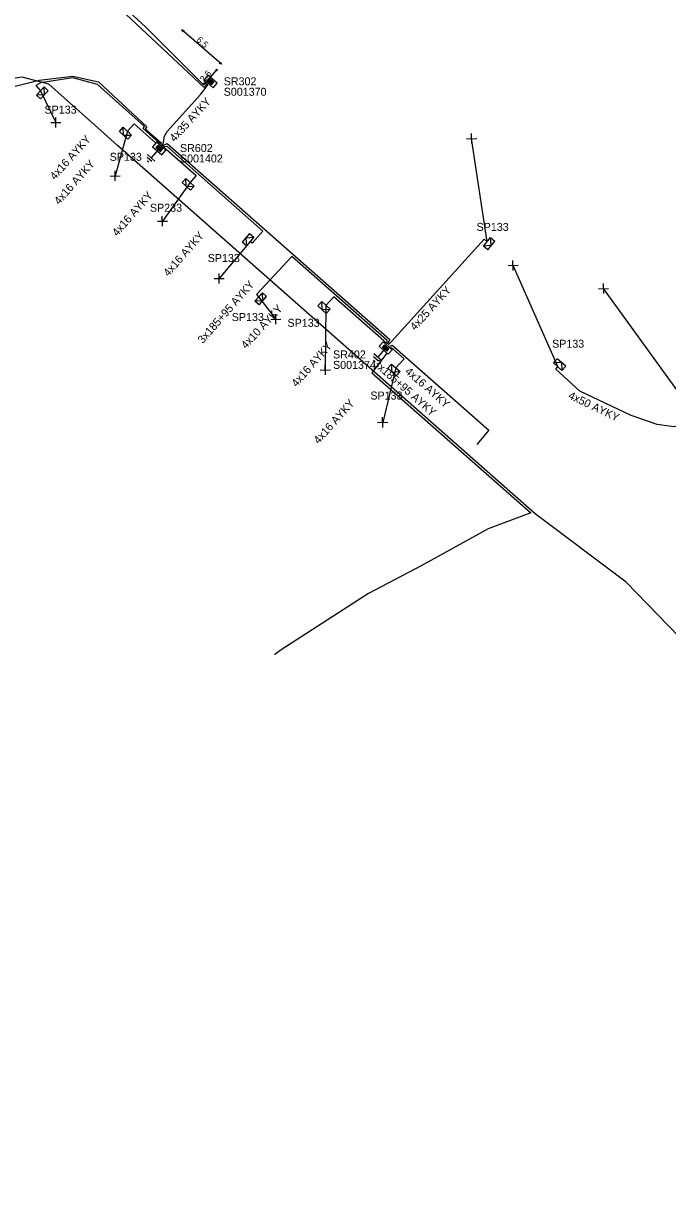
# Model space of a CAD drawing. Extents: x -762284 to -761419, y -1155250 to -1154991.
# Drawn here: x -761812.4 to -761732.3, y -1155246.2 to -1155100.2 of the extents above; entities that cross this region are included whole.
import ezdxf

# ---------------------------------------------------------------- set-up
doc = ezdxf.new("R2010")
doc.units = 0
for name, color, linetype in [('Vrstva 15', 7, 'Continuous'), ('Vrstva 28', 7, 'Continuous'), ('Vrstva 29', 7, 'Continuous'), ('Vrstva 30', 7, 'Continuous'), ('Vrstva 31', 7, 'Continuous'), ('Vrstva 33', 7, 'Continuous'), ('Vrstva 34', 7, 'Continuous'), ('Vrstva 40', 7, 'Continuous'), ('Vrstva 5', 7, 'Continuous'), ('Vrstva 59', 7, 'Continuous'), ('Vrstva 6', 7, 'Continuous')]:
    doc.layers.add(name, color=color, linetype=linetype)

msp = doc.modelspace()

# ---------------------------------------------------------------- linework, layer by layer
at = {"layer": 'Vrstva 15'}
for points in [[(-761795.667, -1155115.926), (-761796.487, -1155116.869)], [(-761796.4, -1155117.355), (-761796.995, -1155116.838)], [(-761796.897, -1155117.341), (-761796.993, -1155117.257)], [(-761796.015, -1155117.279), (-761796.958, -1155116.459)], [(-761796.796, -1155117.428), (-761796.897, -1155117.341)], [(-761767.506, -1155140.716), (-761768.327, -1155141.66)], [(-761768.24, -1155142.146), (-761768.835, -1155141.629)], [(-761768.737, -1155142.131), (-761768.833, -1155142.047)], [(-761767.855, -1155142.07), (-761768.798, -1155141.25)], [(-761768.636, -1155142.219), (-761768.737, -1155142.131)]]:
    msp.add_lwpolyline(points, dxfattribs=at)
at = {"layer": 'Vrstva 28'}
for points in [[(-761789.436, -1155106.625), (-761789.918, -1155107.2)], [(-761789.918, -1155107.2), (-761788.769, -1155108.164)], [(-761789.264, -1155107.017), (-761789.507, -1155107.306)], [(-761789.507, -1155107.306), (-761788.937, -1155107.784)], [(-761789.258, -1155107.083), (-761789.44, -1155107.3)], [(-761789.44, -1155107.3), (-761788.942, -1155107.718)], [(-761788.287, -1155107.589), (-761789.436, -1155106.625)], [(-761789.252, -1155107.15), (-761789.374, -1155107.294)], [(-761789.374, -1155107.294), (-761788.948, -1155107.651)], [(-761789.246, -1155107.216), (-761789.307, -1155107.289)], [(-761789.307, -1155107.289), (-761788.954, -1155107.585)], [(-761788.694, -1155107.495), (-761789.264, -1155107.017)], [(-761788.76, -1155107.501), (-761789.258, -1155107.083)], [(-761788.827, -1155107.507), (-761789.252, -1155107.15)], [(-761788.893, -1155107.512), (-761789.246, -1155107.216)], [(-761788.955, -1155107.522), (-761789.245, -1155107.279)], [(-761788.954, -1155107.585), (-761788.893, -1155107.512)], [(-761788.948, -1155107.651), (-761788.827, -1155107.507)], [(-761788.942, -1155107.718), (-761788.76, -1155107.501)], [(-761788.937, -1155107.784), (-761788.694, -1155107.495)], [(-761788.769, -1155108.164), (-761788.287, -1155107.589)], [(-761795.812, -1155114.947), (-761796.304, -1155115.513)], [(-761796.304, -1155115.513), (-761795.172, -1155116.497)], [(-761795.652, -1155115.329), (-761795.9, -1155115.614)], [(-761795.9, -1155115.614), (-761795.338, -1155116.103)], [(-761795.647, -1155115.396), (-761795.833, -1155115.61)], [(-761795.833, -1155115.61), (-761795.343, -1155116.036)], [(-761794.68, -1155115.931), (-761795.812, -1155114.947)], [(-761795.642, -1155115.463), (-761795.766, -1155115.605)], [(-761795.766, -1155115.605), (-761795.347, -1155115.969)], [(-761795.638, -1155115.529), (-761795.7, -1155115.6)], [(-761795.7, -1155115.6), (-761795.352, -1155115.903)], [(-761795.09, -1155115.817), (-761795.652, -1155115.329)], [(-761795.157, -1155115.822), (-761795.647, -1155115.396)], [(-761795.223, -1155115.827), (-761795.642, -1155115.463)], [(-761795.29, -1155115.831), (-761795.638, -1155115.529)], [(-761795.637, -1155115.592), (-761795.352, -1155115.84)], [(-761795.352, -1155115.903), (-761795.29, -1155115.831)], [(-761795.347, -1155115.969), (-761795.223, -1155115.827)], [(-761795.343, -1155116.036), (-761795.157, -1155115.822)], [(-761795.338, -1155116.103), (-761795.09, -1155115.817)], [(-761795.172, -1155116.497), (-761794.68, -1155115.931)], [(-761767.652, -1155139.737), (-761768.144, -1155140.303)], [(-761766.52, -1155140.721), (-761767.652, -1155139.737)], [(-761768.144, -1155140.303), (-761767.012, -1155141.287)], [(-761767.491, -1155140.119), (-761767.739, -1155140.405)], [(-761767.739, -1155140.405), (-761767.177, -1155140.893)], [(-761767.486, -1155140.186), (-761767.672, -1155140.4)], [(-761767.672, -1155140.4), (-761767.182, -1155140.826)], [(-761767.482, -1155140.253), (-761767.606, -1155140.395)], [(-761767.606, -1155140.395), (-761767.187, -1155140.759)], [(-761767.477, -1155140.319), (-761767.539, -1155140.391)], [(-761767.539, -1155140.391), (-761767.191, -1155140.693)], [(-761766.929, -1155140.608), (-761767.491, -1155140.119)], [(-761766.996, -1155140.612), (-761767.486, -1155140.186)], [(-761767.063, -1155140.617), (-761767.482, -1155140.253)], [(-761767.129, -1155140.622), (-761767.477, -1155140.319)], [(-761767.477, -1155140.382), (-761767.192, -1155140.63)], [(-761767.191, -1155140.693), (-761767.129, -1155140.622)], [(-761767.187, -1155140.759), (-761767.063, -1155140.617)], [(-761767.182, -1155140.826), (-761766.996, -1155140.612)], [(-761767.177, -1155140.893), (-761766.929, -1155140.608)], [(-761767.012, -1155141.287), (-761766.52, -1155140.721)]]:
    msp.add_lwpolyline(points, dxfattribs=at)
at = {"layer": 'Vrstva 31'}
for points in [[(-761810.227, -1155109.562), (-761810.739, -1155109.084), (-761809.784, -1155108.06), (-761809.273, -1155108.538)], [(-761809.75, -1155109.05), (-761810.739, -1155109.084)], [(-761810.227, -1155109.562), (-761809.273, -1155108.538)], [(-761809.75, -1155109.05), (-761809.784, -1155108.06)], [(-761800.432, -1155113.602), (-761799.954, -1155113.091), (-761798.931, -1155114.045), (-761799.408, -1155114.557)], [(-761799.92, -1155114.08), (-761799.954, -1155113.091)], [(-761800.432, -1155113.602), (-761799.408, -1155114.557)], [(-761799.92, -1155114.08), (-761798.931, -1155114.045)], [(-761792.642, -1155119.963), (-761792.165, -1155119.451), (-761791.141, -1155120.405), (-761791.618, -1155120.917)], [(-761792.642, -1155119.963), (-761791.618, -1155120.917)], [(-761792.13, -1155120.44), (-761792.165, -1155119.451)], [(-761792.13, -1155120.44), (-761791.141, -1155120.405)], [(-761784.257, -1155126.29), (-761785.175, -1155127.346)], [(-761784.257, -1155126.29), (-761783.729, -1155126.749), (-761784.647, -1155127.806), (-761785.175, -1155127.346)], [(-761784.716, -1155126.818), (-761783.729, -1155126.749)], [(-761784.716, -1155126.818), (-761784.647, -1155127.806)], [(-761754.655, -1155128.309), (-761755.191, -1155127.859), (-761754.292, -1155126.787), (-761753.755, -1155127.237)], [(-761754.205, -1155127.773), (-761755.191, -1155127.859)], [(-761754.655, -1155128.309), (-761753.755, -1155127.237)], [(-761754.205, -1155127.773), (-761754.292, -1155126.787)], [(-761783.08, -1155135.161), (-761783.6, -1155134.693), (-761782.663, -1155133.652), (-761782.143, -1155134.12)], [(-761782.612, -1155134.641), (-761782.663, -1155133.652)], [(-761782.612, -1155134.641), (-761783.6, -1155134.693)], [(-761783.08, -1155135.161), (-761782.143, -1155134.12)], [(-761775.752, -1155135.253), (-761775.274, -1155134.741), (-761774.25, -1155135.696), (-761774.728, -1155136.208)], [(-761775.752, -1155135.253), (-761774.728, -1155136.208)], [(-761775.24, -1155135.731), (-761775.274, -1155134.741)], [(-761775.24, -1155135.731), (-761774.25, -1155135.696)], [(-761767.061, -1155143.03), (-761766.593, -1155142.51), (-761765.553, -1155143.447), (-761766.021, -1155143.967)], [(-761766.541, -1155143.499), (-761766.593, -1155142.51)], [(-761744.96, -1155142.762), (-761745.42, -1155143.29), (-761746.476, -1155142.372), (-761746.017, -1155141.844)], [(-761745.489, -1155142.303), (-761746.476, -1155142.372)], [(-761744.96, -1155142.762), (-761746.017, -1155141.844)], [(-761745.489, -1155142.303), (-761745.42, -1155143.29)], [(-761767.061, -1155143.03), (-761766.021, -1155143.967)], [(-761766.541, -1155143.499), (-761765.553, -1155143.447)]]:
    msp.add_lwpolyline(points, dxfattribs=at)
at = {"layer": 'Vrstva 34'}
for points in [[(-761808.329, -1155113.125), (-761808.351, -1155111.875)], [(-761808.965, -1155112.511), (-761807.715, -1155112.489)], [(-761757.275, -1155114.501), (-761756.025, -1155114.479)], [(-761756.639, -1155115.115), (-761756.661, -1155113.865)], [(-761801.585, -1155119.141), (-761800.335, -1155119.119)], [(-761800.949, -1155119.755), (-761800.971, -1155118.505)], [(-761795.715, -1155124.761), (-761794.465, -1155124.739)], [(-761795.079, -1155125.375), (-761795.101, -1155124.125)], [(-761752.125, -1155130.261), (-761750.875, -1155130.239)], [(-761751.489, -1155130.875), (-761751.511, -1155129.625)], [(-761788.655, -1155131.891), (-761787.405, -1155131.869)], [(-761788.019, -1155132.505), (-761788.041, -1155131.255)], [(-761740.875, -1155133.141), (-761739.625, -1155133.119)], [(-761740.239, -1155133.755), (-761740.261, -1155132.505)], [(-761780.989, -1155137.565), (-761781.011, -1155136.315)], [(-761781.625, -1155136.951), (-761780.375, -1155136.929)], [(-761774.829, -1155143.865), (-761774.851, -1155142.615)], [(-761775.465, -1155143.251), (-761774.215, -1155143.229)], [(-761768.335, -1155149.761), (-761767.085, -1155149.739)], [(-761767.699, -1155150.375), (-761767.721, -1155149.125)]]:
    msp.add_lwpolyline(points, dxfattribs=at)
at = {"layer": 'Vrstva 40'}
for points in [[(-761792.672, -1155100.988), (-761792.414, -1155101.068), (-761792.549, -1155101.228)], [(-761788.268, -1155105.848), (-761788.348, -1155106.106), (-761788.508, -1155105.971)], [(-761787.748, -1155105.252), (-761788.006, -1155105.172), (-761787.872, -1155105.012)], [(-761789.972, -1155107.812), (-761789.892, -1155107.554), (-761789.732, -1155107.689)]]:
    msp.add_lwpolyline(points, close=True, dxfattribs=at)
for points in [[(-761787.75, -1155105.25), (-761792.67, -1155100.99)], [(-761788.27, -1155105.85), (-761789.97, -1155107.81)]]:
    msp.add_lwpolyline(points, dxfattribs=at)
at = {"layer": 'Vrstva 5'}
for points in [[(-761789.53, -1155107.69), (-761789.92, -1155108.14), (-761837.9, -1155063.24), (-761877.84, -1155029.75), (-761879.95, -1155027.01), (-761882.5, -1155025.98), (-761882.38, -1155025.37)], [(-761789.65, -1155107.58), (-761789.97, -1155107.81), (-761794.53, -1155103.25), (-761797.17, -1155100.64), (-761801.59, -1155096.53), (-761801.33, -1155094.57), (-761800.37, -1155092.21), (-761797.07, -1155090.87), (-761792.02, -1155089.66), (-761789.02, -1155089.12), (-761787.3, -1155090.45), (-761786.97, -1155090.93), (-761787.05, -1155090.2), (-761786.17, -1155089.25), (-761779.7, -1155087.13), (-761771.35, -1155084.63), (-761765.46, -1155082.64), (-761758.32, -1155079.63), (-761748.98, -1155075.15), (-761744.02, -1155072.9), (-761741.27, -1155074.83)], [(-761855.05, -1155147.98), (-761855.07, -1155147.93), (-761855.65, -1155147.35), (-761836.57, -1155127.39), (-761819.77, -1155109.53), (-761810.41, -1155107.25), (-761806.23, -1155106.72), (-761803.04, -1155107.44), (-761797.02, -1155113.03), (-761797.22, -1155113.26), (-761795.25, -1155115.01), (-761795.31, -1155115.22)], [(-761676.7, -1155245.18), (-761673.46, -1155246.2), (-761670.79, -1155237.14), (-761684.52, -1155223.2), (-761704.2, -1155203.38), (-761720.29, -1155187.3), (-761737.44, -1155169.6), (-761748.74, -1155161.1), (-761800.66, -1155115.37), (-761802.76, -1155113.49), (-761809.21, -1155107.71), (-761812.53, -1155106.85), (-761816.77, -1155107.49), (-761819.95, -1155109.3), (-761836.79, -1155127.18), (-761844.99, -1155135.76), (-761850.45, -1155130.54), (-761834.24, -1155112.53), (-761834.72, -1155111.94), (-761834.75, -1155111.9)], [(-761795.41, -1155115.13), (-761795.48, -1155115.03), (-761797.49, -1155113.24), (-761797.32, -1155112.99), (-761803.15, -1155107.75), (-761806.22, -1155106.96), (-761810.23, -1155107.56), (-761810.84, -1155107.91), (-761810.26, -1155108.57)], [(-761795.22, -1155115.3), (-761794.98, -1155115.16), (-761794.85, -1155114.17), (-761794.52, -1155113.62), (-761790.3, -1155108.99), (-761789.42, -1155107.78)], [(-761796, -1155114.97), (-761798.62, -1155112.64), (-761799.44, -1155113.57)], [(-761795.12, -1155115.39), (-761794.51, -1155115.09), (-761766.83, -1155139.47), (-761767.03, -1155139.84), (-761767.11, -1155140.05)], [(-761795.02, -1155115.47), (-761794.56, -1155115.44), (-761782.59, -1155125.99), (-761783.95, -1155127.5), (-761784.19, -1155127.28)], [(-761794.92, -1155115.56), (-761794.61, -1155115.8), (-761790.89, -1155119.08), (-761791.65, -1155119.93)], [(-761767.01, -1155140.13), (-761766.57, -1155139.65), (-761755.11, -1155126.99), (-761754.74, -1155127.32)], [(-761767.2, -1155139.96), (-761767.15, -1155139.6), (-761778.99, -1155129.13), (-761783.39, -1155133.88), (-761783.13, -1155134.17)], [(-761767.3, -1155139.88), (-761767.56, -1155139.62), (-761773.78, -1155134.15), (-761774.76, -1155135.22)], [(-761697.08, -1155137.44), (-761697.24, -1155137.56), (-761710.9, -1155142.98), (-761711.29, -1155142.7), (-761711.3, -1155143.11), (-761728.16, -1155149.69), (-761728.55, -1155149.31), (-761728.54, -1155149.81), (-761730.53, -1155150.11), (-761731.5, -1155150.3), (-761733.59, -1155150), (-761736.81, -1155148.91), (-761743.2, -1155145.87), (-761746.18, -1155143.14), (-761745.95, -1155142.83)], [(-761767.18, -1155141.17), (-761769.06, -1155143.59), (-761749.31, -1155160.99), (-761754.59, -1155162.99), (-761762.93, -1155167.58), (-761769.49, -1155171.01), (-761780.32, -1155178), (-761781.11, -1155178.6), (-761781.15, -1155178.55)], [(-761766.81, -1155140.3), (-761766.51, -1155140.16), (-761766.22, -1155140.42), (-761754.5, -1155150.72), (-761755.99, -1155152.5)], [(-761766.72, -1155140.39), (-761766.43, -1155140.62), (-761765.05, -1155141.84), (-761766.07, -1155142.98)]]:
    msp.add_lwpolyline(points, dxfattribs=at)
at = {"layer": 'Vrstva 59'}
for points in [[(-761810.26, -1155108.57), (-761808.34, -1155112.5)], [(-761799.44, -1155113.57), (-761800.96, -1155119.13)], [(-761754.74, -1155127.32), (-761756.65, -1155114.5)], [(-761791.65, -1155119.93), (-761795.09, -1155124.75)], [(-761784.19, -1155127.28), (-761788.03, -1155131.88)], [(-761745.95, -1155142.83), (-761751.5, -1155130.25)], [(-761728.55, -1155149.31), (-761740.25, -1155133.13)], [(-761783.13, -1155134.17), (-761781, -1155136.94)], [(-761774.76, -1155135.22), (-761774.84, -1155143.25)], [(-761766.07, -1155142.98), (-761767.71, -1155149.75)]]:
    msp.add_lwpolyline(points, dxfattribs=at)

# ---------------------------------------------------------------- texts
at = {"layer": 'Vrstva 29'}
for s, p in [('S001370', (-761787.47, -1155109.17)), ('S001402', (-761792.91, -1155117.46)), ('S001374', (-761773.88, -1155143.11))]:
    msp.add_text(s, height=0.9943, dxfattribs=at).set_placement(p)
at = {"layer": 'Vrstva 30'}
for s, p in [('SR302', (-761787.47, -1155107.87)), ('SR602', (-761792.91, -1155116.16)), ('SR402', (-761773.88, -1155141.81))]:
    msp.add_text(s, height=0.9943, dxfattribs=at).set_placement(p)
at = {"layer": 'Vrstva 33'}
for s, p in [('SP133', (-761809.75, -1155111.39)), ('SP133', (-761801.64, -1155117.25)), ('SP233', (-761796.64, -1155123.58)), ('SP133', (-761756.04, -1155125.96)), ('SP133', (-761789.46, -1155129.83)), ('SP133', (-761786.47, -1155137.16)), ('SP133', (-761779.54, -1155137.88)), ('SP133', (-761746.65, -1155140.48)), ('SP133', (-761769.24, -1155146.92))]:
    msp.add_text(s, height=0.9943, dxfattribs=at).set_placement(p)
at = {"layer": 'Vrstva 40'}
for s, rotation, p in [('6,5', 319.108, (-761790.93, -1155102.33)), ('2,6', 49.1119, (-761789.91, -1155107.55))]:
    msp.add_text(s, height=0.7954, rotation=rotation, dxfattribs=at).set_placement(p)
at = {"layer": 'Vrstva 6'}
for s, height, rotation, p in [('4x35 AYKY', 0.9943, 47.65248, (-761793.58, -1155114.98)), ('4x16 AYKY', 0.9943, 48.06713, (-761808.46, -1155119.7)), ('4x16 AYKY', 0.9943, 48.38417, (-761807.93, -1155122.78)), ('4x16 AYKY', 0.9943, 48.60847, (-761800.71, -1155126.71)), ('4x16 AYKY', 0.9943, 48.62052, (-761794.34, -1155131.71)), ('3x185+95 AYKY', 0.99429, 48.6199, (-761790.07, -1155140.04)), ('4x25 AYKY', 0.9943, 47.82224, (-761763.69, -1155138.42)), ('4x10 AYKY', 0.9943, 47.17807, (-761784.7, -1155140.7)), ('4x16 AYKY', 0.9943, 48.62606, (-761778.42, -1155145.43)), ('3x185+95 AYKY', 0.99429, 318.62641, (-761768.95, -1155142.6)), ('4x16 AYKY', 0.9943, 318.65101, (-761765.01, -1155143.55)), ('4x16 AYKY', 0.9943, 48.25165, (-761775.67, -1155152.51)), ('4x50 AYKY', 0.9943, 334.48962, (-761744.73, -1155146.75))]:
    msp.add_text(s, height=height, rotation=rotation, dxfattribs=at).set_placement(p)

doc.saveas('drawing.dxf')
